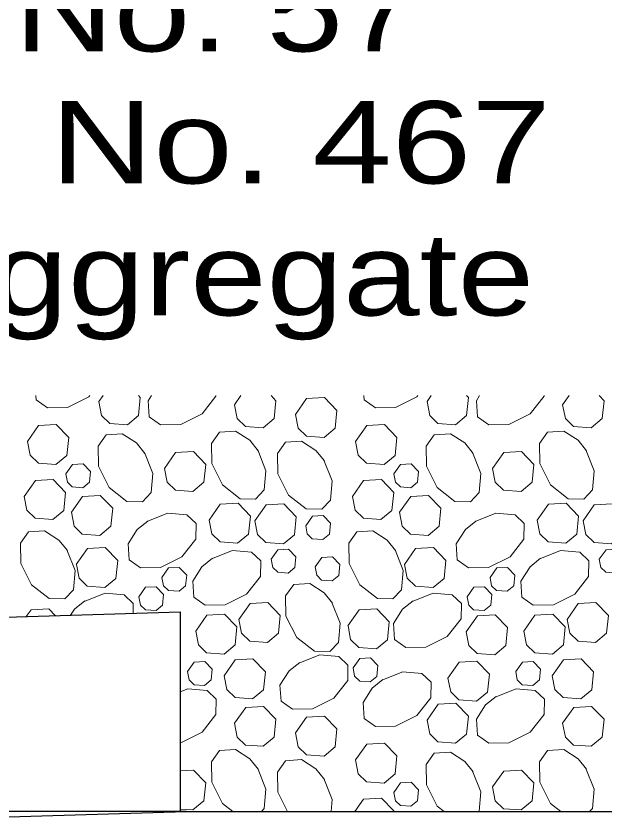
# Model space of a CAD drawing. Extents: x 1083.1 to 1117.1, y 697.4 to 741.4.
# Drawn here: x 1099.721 to 1100.838, y 704.268 to 705.8 of the extents above; entities that cross this region are included whole.
import ezdxf
from ezdxf.enums import TextEntityAlignment as Align

# ---------------------------------------------------------------- set-up
doc = ezdxf.new("R2010")
doc.units = 0
doc.header["$LTSCALE"] = 0.062
doc.linetypes.add('LONG_DASHED', pattern=[7.5, 6, -1.5])
doc.layers.add('1', color=7, linetype='Continuous', lineweight=13)

msp = doc.modelspace()

# ---------------------------------------------------------------- linework, layer by layer
at = {"layer": '1'}
for p, q in [((1099.87833, 705.06908), (1099.88625, 705.08042)), ((1100.13575, 705.06325), (1100.14783, 705.08042)), ((1100.501, 705.06908), (1100.50892, 705.08042)), ((1100.75833, 705.06325), (1100.7705, 705.08042))]:
    msp.add_line(p, q, dxfattribs=at)
at = {"layer": '1', "lineweight": 25}
msp.add_line((1093.13575, 704.08392), (1100.04408, 704.29175), dxfattribs=at)
for points in [[(1100.04408, 704.29175), (1101.19942, 704.29175), (1101.19942, 706.63767)], [(1098.91383, 705.41058), (1098.91383, 704.63642), (1100.03275, 704.67008), (1100.03275, 704.29175)]]:
    msp.add_lwpolyline(points, dxfattribs=at)
at = {"layer": '1'}
for points in [[(1099.86117, 705.08042), (1099.85925, 705.07792), (1099.81867, 705.05775), (1099.78058, 705.057), (1099.75908, 705.07233), (1099.7585, 705.08042)], [(1099.95325, 705.08042), (1099.95675, 705.07675), (1099.95342, 705.04267), (1099.9325, 705.02533), (1099.89917, 705.02775), (1099.88342, 705.04292), (1099.87833, 705.06908)], [(1100.1005, 705.08042), (1100.1005, 705.0795), (1100.07417, 705.046), (1100.03367, 705.02567), (1099.9955, 705.02508), (1099.974, 705.04033), (1099.972, 705.07075), (1099.97817, 705.08042)], [(1100.205, 705.08042), (1100.21417, 705.07083), (1100.21075, 705.03683), (1100.18983, 705.01942), (1100.15658, 705.02183), (1100.14083, 705.037), (1100.13575, 705.06325)], [(1100.48375, 705.08042), (1100.48183, 705.07792), (1100.44133, 705.05775), (1100.40317, 705.057), (1100.38167, 705.07233), (1100.38108, 705.08042)], [(1100.57592, 705.08042), (1100.57942, 705.07675), (1100.576, 705.04267), (1100.55508, 705.02533), (1100.52175, 705.02775), (1100.50608, 705.04292), (1100.501, 705.06908)], [(1100.72317, 705.08042), (1100.72317, 705.0795), (1100.69683, 705.046), (1100.65633, 705.02567), (1100.61817, 705.02508), (1100.59667, 705.04033), (1100.59458, 705.07075), (1100.60075, 705.08042)], [(1100.82758, 705.08042), (1100.83683, 705.07083), (1100.83333, 705.03683), (1100.8125, 705.01942), (1100.77917, 705.02183), (1100.7635, 705.037), (1100.75833, 705.06325)], [(1100.25133, 705.04483), (1100.2725, 705.07483), (1100.30633, 705.07683), (1100.32983, 705.05242), (1100.32642, 705.01842), (1100.30558, 705.001), (1100.27225, 705.00342), (1100.2565, 705.01858), (1100.25142, 705.04475)], [(1099.96475, 704.97233), (1099.98042, 704.93275), (1099.97733, 704.89642), (1099.96083, 704.87917), (1099.93133, 704.87967), (1099.89783, 704.90592), (1099.87758, 704.9465), (1099.87692, 704.98467), (1099.89217, 705.00608), (1099.92258, 705.00817), (1099.94983, 704.99075), (1099.96583, 704.97075)], [(1100.17975, 704.9775), (1100.19542, 704.93792), (1100.19225, 704.90158), (1100.17583, 704.88425), (1100.14633, 704.88483), (1100.11283, 704.91108), (1100.09258, 704.95158), (1100.09192, 704.98975), (1100.10717, 705.01133), (1100.13758, 705.01325), (1100.16483, 704.99592), (1100.18083, 704.97592)], [(1100.58733, 704.97233), (1100.60308, 704.93275), (1100.59992, 704.89642), (1100.5835, 704.87917), (1100.554, 704.87967), (1100.5205, 704.90592), (1100.50025, 704.9465), (1100.49958, 704.98467), (1100.51483, 705.00608), (1100.54525, 705.00817), (1100.5725, 704.99075), (1100.58842, 704.97075)], [(1100.80242, 704.9775), (1100.81808, 704.93792), (1100.81492, 704.90158), (1100.7985, 704.88425), (1100.769, 704.88483), (1100.7355, 704.91108), (1100.71525, 704.95158), (1100.71458, 704.98975), (1100.72983, 705.01133), (1100.76025, 705.01325), (1100.7875, 704.99592), (1100.80342, 704.97592)], [(1100.30517, 704.95825), (1100.32083, 704.91875), (1100.31775, 704.88233), (1100.30133, 704.86508), (1100.27183, 704.86558), (1100.23833, 704.89192), (1100.218, 704.93242), (1100.21742, 704.97058), (1100.23267, 704.99208), (1100.263, 704.99408), (1100.29025, 704.97667), (1100.30617, 704.95675)], [(1100.35933, 704.88917), (1100.38058, 704.91917), (1100.41433, 704.92117), (1100.43783, 704.89675), (1100.43442, 704.86267), (1100.41358, 704.84533), (1100.38025, 704.84775), (1100.3645, 704.86292), (1100.35942, 704.88917)], [(1099.96942, 704.8415), (1100.009, 704.85725), (1100.04533, 704.85408), (1100.06267, 704.83767), (1100.06208, 704.80817), (1100.03583, 704.77467), (1099.99533, 704.75442), (1099.95717, 704.75375), (1099.93558, 704.769), (1099.93367, 704.79942), (1099.951, 704.82667), (1099.971, 704.84258)], [(1100.59208, 704.8415), (1100.63167, 704.85725), (1100.668, 704.85408), (1100.68533, 704.83767), (1100.68475, 704.80817), (1100.6585, 704.77467), (1100.61792, 704.75442), (1100.57983, 704.75375), (1100.55825, 704.769), (1100.55617, 704.79942), (1100.57367, 704.82667), (1100.59367, 704.84258)], [(1099.81758, 704.78808), (1099.83325, 704.7485), (1099.83008, 704.71217), (1099.81375, 704.69492), (1099.78425, 704.69542), (1099.75067, 704.72167), (1099.73042, 704.76217), (1099.72975, 704.80042), (1099.74508, 704.82183), (1099.77542, 704.82392), (1099.80267, 704.80642), (1099.81858, 704.7865)], [(1100.44025, 704.78808), (1100.45592, 704.7485), (1100.45275, 704.71217), (1100.43633, 704.69492), (1100.40683, 704.69542), (1100.37333, 704.72167), (1100.35308, 704.76217), (1100.35242, 704.80042), (1100.36767, 704.82183), (1100.39808, 704.82392), (1100.42533, 704.80642), (1100.44125, 704.7865)], [(1099.8355, 704.76017), (1099.85667, 704.79033), (1099.8905, 704.79225), (1099.914, 704.76792), (1099.91058, 704.73375), (1099.88975, 704.71642), (1099.85642, 704.71883), (1099.84067, 704.73408), (1099.83558, 704.76017)], [(1100.20517, 704.77025), (1100.21792, 704.78825), (1100.23817, 704.7895), (1100.25225, 704.77483), (1100.25025, 704.75442), (1100.23767, 704.744), (1100.21767, 704.74542), (1100.20825, 704.7545), (1100.20525, 704.77025)], [(1100.09225, 704.77092), (1100.13183, 704.78658), (1100.16817, 704.78342), (1100.18542, 704.767), (1100.18492, 704.7375), (1100.15858, 704.70392), (1100.11808, 704.68375), (1100.07992, 704.683), (1100.05842, 704.69825), (1100.05633, 704.72875), (1100.07383, 704.75592), (1100.09383, 704.77192)], [(1100.71483, 704.77092), (1100.75442, 704.78658), (1100.79075, 704.78342), (1100.808, 704.767), (1100.8075, 704.7375), (1100.78125, 704.70392), (1100.74075, 704.68375), (1100.7025, 704.683), (1100.68108, 704.69825), (1100.679, 704.72875), (1100.6965, 704.75592), (1100.71642, 704.77192)], [(1100.3205, 704.68825), (1100.33625, 704.64867), (1100.33308, 704.61233), (1100.31667, 704.59508), (1100.28717, 704.59567), (1100.25367, 704.62183), (1100.23333, 704.66233), (1100.23275, 704.70058), (1100.248, 704.72208), (1100.27842, 704.72408), (1100.30558, 704.70658), (1100.32158, 704.68667)], [(1099.85033, 704.69025), (1099.89, 704.70592), (1099.92633, 704.70275), (1099.94358, 704.68642), (1099.94317, 704.66733)], [(1100.473, 704.69025), (1100.5125, 704.70592), (1100.54892, 704.70275), (1100.56617, 704.68642), (1100.56567, 704.65692), (1100.53942, 704.62342), (1100.49892, 704.60308), (1100.46067, 704.60242), (1100.43925, 704.61775), (1100.43717, 704.64808), (1100.45467, 704.67533), (1100.47458, 704.69125)], [(1099.82458, 704.66375), (1099.832, 704.67533), (1099.852, 704.69125)], [(1100.76667, 704.65608), (1100.78783, 704.68608), (1100.82158, 704.68808), (1100.84508, 704.66367), (1100.84167, 704.62958), (1100.82083, 704.61225), (1100.7875, 704.61467), (1100.77175, 704.62983), (1100.76675, 704.65608)], [(1099.74058, 704.66125), (1099.74958, 704.674), (1099.78333, 704.67583), (1099.79583, 704.66292)], [(1100.351, 704.64383), (1100.37208, 704.674), (1100.40592, 704.67583), (1100.42942, 704.65158), (1100.426, 704.61742), (1100.40517, 704.60008), (1100.37183, 704.6025), (1100.35608, 704.61775), (1100.35108, 704.64383)], [(1100.68458, 704.63392), (1100.70575, 704.66408), (1100.73958, 704.66592), (1100.763, 704.64167), (1100.75967, 704.6075), (1100.73875, 704.59008), (1100.70542, 704.59258), (1100.68967, 704.60783), (1100.68467, 704.63392)], [(1100.0465, 704.557), (1100.05917, 704.575), (1100.0795, 704.57617), (1100.09358, 704.56158), (1100.0915, 704.54108), (1100.079, 704.53075), (1100.05892, 704.53217), (1100.04958, 704.54125), (1100.0465, 704.55692)], [(1100.25783, 704.57325), (1100.29742, 704.58892), (1100.33375, 704.58583), (1100.351, 704.56933), (1100.3505, 704.53983), (1100.32425, 704.50633), (1100.28367, 704.48608), (1100.2455, 704.48542), (1100.224, 704.50067), (1100.22192, 704.53108), (1100.23942, 704.55833), (1100.25942, 704.57425)], [(1100.66917, 704.557), (1100.68183, 704.575), (1100.70217, 704.57617), (1100.71625, 704.56158), (1100.71417, 704.54108), (1100.70167, 704.53075), (1100.68158, 704.53217), (1100.67225, 704.54125), (1100.66917, 704.55692)], [(1100.4155, 704.54075), (1100.455, 704.55642), (1100.49142, 704.55333), (1100.50867, 704.53683), (1100.50817, 704.50733), (1100.48183, 704.47383), (1100.44133, 704.45358), (1100.40317, 704.45292), (1100.38167, 704.46817), (1100.37958, 704.49867), (1100.39708, 704.52583), (1100.417, 704.54175)], [(1100.03275, 704.51858), (1100.04742, 704.52442), (1100.08375, 704.52125), (1100.101, 704.50483), (1100.1005, 704.47533), (1100.07417, 704.44183), (1100.03367, 704.42158), (1100.03275, 704.42158)], [(1100.6305, 704.50875), (1100.67, 704.52442), (1100.70642, 704.52125), (1100.72367, 704.50483), (1100.72317, 704.47533), (1100.69683, 704.44183), (1100.65633, 704.42158), (1100.61817, 704.42092), (1100.59667, 704.43617), (1100.59458, 704.46658), (1100.61208, 704.49383), (1100.632, 704.50975)], [(1100.25133, 704.44067), (1100.2725, 704.47067), (1100.30633, 704.47267), (1100.32983, 704.44833), (1100.32642, 704.41425), (1100.30558, 704.39683), (1100.27225, 704.39925), (1100.2565, 704.4145), (1100.25142, 704.44067)], [(1100.13225, 704.29175), (1100.11283, 704.30692), (1100.09258, 704.34742), (1100.09192, 704.38567), (1100.10717, 704.40717), (1100.13758, 704.40917), (1100.16483, 704.39175), (1100.18083, 704.37175)], [(1100.75492, 704.29175), (1100.7355, 704.30692), (1100.71525, 704.34742), (1100.71458, 704.38567), (1100.72983, 704.40717), (1100.76025, 704.40917), (1100.7875, 704.39175), (1100.80342, 704.37175)], [(1100.53342, 704.29175), (1100.5205, 704.30183), (1100.50025, 704.34233), (1100.49958, 704.38058), (1100.51483, 704.402), (1100.54525, 704.40408), (1100.5725, 704.38658), (1100.58842, 704.36667)], [(1100.23625, 704.29175), (1100.218, 704.32825), (1100.21742, 704.3665), (1100.23267, 704.38792), (1100.263, 704.39), (1100.29025, 704.3725), (1100.30617, 704.35258)], [(1100.03275, 704.36892), (1100.05767, 704.37033), (1100.08125, 704.34592), (1100.07775, 704.31192), (1100.05692, 704.2945), (1100.03275, 704.29625)], [(1100.17975, 704.37333), (1100.19542, 704.33375), (1100.19225, 704.29742), (1100.18683, 704.29175)], [(1100.58733, 704.36817), (1100.60308, 704.32867), (1100.59992, 704.29225), (1100.59942, 704.29175)], [(1100.80242, 704.37333), (1100.81808, 704.33375), (1100.81492, 704.29742), (1100.8095, 704.29175)], [(1100.30517, 704.35408), (1100.32083, 704.31458), (1100.31892, 704.29175)], [(1100.36408, 704.29175), (1100.38058, 704.31508), (1100.41433, 704.317), (1100.43783, 704.29267), (1100.43775, 704.29175)]]:
    msp.add_lwpolyline(points, dxfattribs=at)
for points in [[(1099.74275, 704.99358), (1099.76383, 705.02375), (1099.79758, 705.02558), (1099.82117, 705.00133), (1099.81767, 704.96717), (1099.79683, 704.94975), (1099.7635, 704.95225), (1099.74783, 704.9675)], [(1100.36533, 704.99358), (1100.3865, 705.02375), (1100.42025, 705.02558), (1100.44367, 705.00133), (1100.44033, 704.96717), (1100.4195, 704.94975), (1100.38608, 704.95225), (1100.3705, 704.9675)], [(1100.00275, 704.94242), (1100.02392, 704.9725), (1100.05767, 704.97442), (1100.08125, 704.95008), (1100.07775, 704.916), (1100.05692, 704.89867), (1100.02358, 704.901), (1100.00792, 704.91625)], [(1100.62542, 704.94242), (1100.6465, 704.9725), (1100.68033, 704.97442), (1100.70375, 704.95008), (1100.70042, 704.916), (1100.67958, 704.89867), (1100.64617, 704.901), (1100.6305, 704.91625)], [(1099.81542, 704.93192), (1099.82808, 704.95), (1099.84833, 704.95117), (1099.86242, 704.93658), (1099.86042, 704.91608), (1099.84792, 704.90567), (1099.82783, 704.90717), (1099.8185, 704.91625)], [(1100.438, 704.93192), (1100.45075, 704.95), (1100.471, 704.95117), (1100.48508, 704.93658), (1100.483, 704.91608), (1100.4705, 704.90567), (1100.4505, 704.90717), (1100.44108, 704.91625)], [(1099.73683, 704.88917), (1099.75792, 704.91917), (1099.79175, 704.92117), (1099.81517, 704.89675), (1099.81175, 704.86267), (1099.79092, 704.84533), (1099.75758, 704.84775), (1099.74183, 704.86292)], [(1099.82617, 704.85925), (1099.84733, 704.88933), (1099.88108, 704.89125), (1099.90458, 704.86692), (1099.90117, 704.83283), (1099.88033, 704.81542), (1099.84692, 704.81783), (1099.83125, 704.83308)], [(1100.44883, 704.85925), (1100.47, 704.88933), (1100.50375, 704.89125), (1100.52717, 704.86692), (1100.52375, 704.83283), (1100.50292, 704.81542), (1100.46958, 704.81783), (1100.45392, 704.83308)], [(1100.08742, 704.84425), (1100.10858, 704.87442), (1100.14233, 704.87633), (1100.16583, 704.852), (1100.16242, 704.81783), (1100.14158, 704.80058), (1100.10817, 704.80292), (1100.0925, 704.81817)], [(1100.17442, 704.843), (1100.19558, 704.87317), (1100.22933, 704.87508), (1100.25283, 704.85075), (1100.2495, 704.81658), (1100.22858, 704.79925), (1100.19525, 704.80167), (1100.17958, 704.81692)], [(1100.71008, 704.84425), (1100.73125, 704.87442), (1100.765, 704.87633), (1100.78842, 704.852), (1100.78508, 704.81783), (1100.76417, 704.80058), (1100.73083, 704.80292), (1100.71517, 704.81817)], [(1100.79708, 704.843), (1100.81825, 704.87317), (1100.852, 704.87508), (1100.8755, 704.85075), (1100.87217, 704.81658), (1100.85117, 704.79925), (1100.81783, 704.80167), (1100.80217, 704.81692)], [(1100.27075, 704.83375), (1100.28342, 704.85175), (1100.30367, 704.85292), (1100.31775, 704.83833), (1100.31575, 704.81783), (1100.30325, 704.8075), (1100.28317, 704.80892), (1100.27375, 704.818)], [(1100.45817, 704.76017), (1100.47933, 704.79033), (1100.51317, 704.79225), (1100.53658, 704.76792), (1100.53325, 704.73375), (1100.51242, 704.71642), (1100.479, 704.71883), (1100.46333, 704.73408)], [(1100.82783, 704.77025), (1100.84058, 704.78825), (1100.86083, 704.7895), (1100.87492, 704.77483), (1100.87283, 704.75442), (1100.86033, 704.744), (1100.84033, 704.74542), (1100.83092, 704.7545)], [(1100.28858, 704.75542), (1100.30125, 704.77342), (1100.32158, 704.77458), (1100.33558, 704.76), (1100.33358, 704.7395), (1100.32108, 704.72917), (1100.301, 704.73058), (1100.29167, 704.73967)], [(1099.99792, 704.73558), (1100.01058, 704.75358), (1100.03083, 704.75475), (1100.04492, 704.74017), (1100.04292, 704.71967), (1100.03042, 704.70933), (1100.01042, 704.71075), (1100.001, 704.71983)], [(1100.62058, 704.73558), (1100.63325, 704.75358), (1100.6535, 704.75475), (1100.66758, 704.74017), (1100.66558, 704.71967), (1100.653, 704.70933), (1100.633, 704.71075), (1100.62358, 704.71983)], [(1099.95425, 704.69883), (1099.967, 704.71692), (1099.98725, 704.718), (1100.00125, 704.7035), (1099.99925, 704.68292), (1099.98675, 704.67258), (1099.96675, 704.674), (1099.95733, 704.68308)], [(1100.57692, 704.69883), (1100.58958, 704.71692), (1100.60983, 704.718), (1100.62392, 704.7035), (1100.62192, 704.68292), (1100.60942, 704.67258), (1100.58942, 704.674), (1100.58, 704.68308)], [(1100.14408, 704.65608), (1100.16517, 704.68608), (1100.199, 704.68808), (1100.22242, 704.66367), (1100.219, 704.62958), (1100.19817, 704.61225), (1100.16483, 704.61467), (1100.14917, 704.62983)], [(1100.062, 704.63392), (1100.08317, 704.66408), (1100.11692, 704.66592), (1100.14033, 704.64167), (1100.137, 704.6075), (1100.11617, 704.59008), (1100.08275, 704.59258), (1100.06717, 704.60783)], [(1100.5755, 704.63267), (1100.59667, 704.66283), (1100.63042, 704.66467), (1100.65392, 704.64042), (1100.6505, 704.60625), (1100.62958, 704.58892), (1100.59625, 704.59133), (1100.58058, 704.60658)], [(1100.11583, 704.54917), (1100.137, 704.57925), (1100.17075, 704.58117), (1100.19425, 704.55683), (1100.19083, 704.52267), (1100.16992, 704.50542), (1100.13667, 704.50775), (1100.12092, 704.523)], [(1100.36067, 704.56392), (1100.37333, 704.58192), (1100.39358, 704.58308), (1100.40767, 704.5685), (1100.40567, 704.548), (1100.39317, 704.53767), (1100.37317, 704.53908), (1100.36367, 704.54817)], [(1100.54075, 704.54458), (1100.56192, 704.57467), (1100.59567, 704.57658), (1100.61925, 704.55225), (1100.61583, 704.51817), (1100.59492, 704.50083), (1100.56158, 704.50317), (1100.54592, 704.51842)], [(1100.7385, 704.54917), (1100.75967, 704.57925), (1100.79342, 704.58117), (1100.81692, 704.55683), (1100.81342, 704.52267), (1100.79258, 704.50542), (1100.75925, 704.50775), (1100.74358, 704.523)], [(1100.13575, 704.45908), (1100.15692, 704.48917), (1100.19067, 704.49108), (1100.21417, 704.46675), (1100.21075, 704.43267), (1100.18983, 704.41533), (1100.15658, 704.41767), (1100.14083, 704.43292)], [(1100.501, 704.465), (1100.52217, 704.49508), (1100.55592, 704.497), (1100.57942, 704.47267), (1100.576, 704.4385), (1100.55508, 704.42125), (1100.52175, 704.42358), (1100.50608, 704.43883)], [(1100.75833, 704.45908), (1100.7795, 704.48917), (1100.81325, 704.49108), (1100.83683, 704.46675), (1100.83333, 704.43267), (1100.8125, 704.41533), (1100.77917, 704.41767), (1100.7635, 704.43292)], [(1100.36533, 704.38942), (1100.3865, 704.41958), (1100.42025, 704.42142), (1100.44367, 704.39717), (1100.44033, 704.363), (1100.4195, 704.34567), (1100.38608, 704.34808), (1100.3705, 704.36333)], [(1100.62542, 704.33833), (1100.6465, 704.36833), (1100.68033, 704.37033), (1100.70375, 704.34592), (1100.70042, 704.31192), (1100.67958, 704.2945), (1100.64617, 704.29692), (1100.6305, 704.31208)], [(1100.438, 704.32783), (1100.45075, 704.34583), (1100.471, 704.34708), (1100.48508, 704.33242), (1100.483, 704.31192), (1100.4705, 704.30158), (1100.4505, 704.303), (1100.44108, 704.31208)]]:
    msp.add_lwpolyline(points, close=True, dxfattribs=at)
at = {"layer": '1', "linetype": 'LONG_DASHED', "lineweight": 25}
msp.add_lwpolyline([(1100.04408, 704.29175), (1098.91383, 704.29175), (1098.91383, 704.63642)], dxfattribs=at)

# ---------------------------------------------------------------- texts
at = {"layer": '1'}
for s, width, p in [('No. 57', 1.25, (1100.10246, 705.73342)), ('or No. 467', 1.3, (1100.1025, 705.483)), ('Aggregate', 1.25, (1100.1025, 705.23258))]:
    msp.add_text(s, height=0.156, dxfattribs=dict(at, width=width)).set_placement(p, align=Align.CENTER)

doc.saveas('drawing.dxf')
